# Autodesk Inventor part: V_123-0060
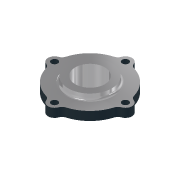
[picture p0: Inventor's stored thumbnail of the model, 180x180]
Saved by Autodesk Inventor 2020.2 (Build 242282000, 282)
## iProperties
Created: 2006-02
Part Number: V_123-0060
Document SubType Name: Modeling
Designer: F.Stasiak
Description: Pokrywka typ1
Material: St 4S
Project: Przekładnia X51
Mass: 230.761 g
Surface Area: 113.991 cm^2
Volume: 29.3963 cm^3
Density: 7.85 g/cm^3
Appearance: Brąz armatni (nowy/polerowany)
Manager: www.cadconsulting.pl
Company: Fabian Stasiak CAD Consulting
Author: F.Stasiak
Subject: Zbiór ćwiczeń. Autodesk Inventor 2020. Kurs podstawowy
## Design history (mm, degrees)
sketch "Szkic1"
  geometry: C1 r 32.5 at (0, -38.423); A1 r 23.5 centre (0, -38.423) between (0, -14.923) and (0, -61.923) reference
  constraints: 1 centre point, 1 coincident
  dimensions: "d0" = 65 diameter of C1
extrude "Wyciągnięcie proste1" new body sketch "Szkic1" distance "d1" = 8; taper "d2" = 0 deg
sketch "Szkic2"
  geometry: C1 r 16.02 at (0, 0) reference
extrude "Wyciągnięcie proste2" join sketch "Szkic2" distance "d3" = 9.6; taper "d4" = 0 deg
sketch "Szkic4"
  geometry: C1 r 12.5 at (0, 0) reference; C2 r 13.5 at (0, 0)
  constraints: 1 centre point, 1 coincident
  dimensions: "d30" = 27 diameter of C2
extrude "Wyciągnięcie proste4" cut sketch "Szkic4" extent not by distance; stored distance "d7" = 6.5; taper "d8" = 0 deg
fillet "Zaokrąglenie1" dims "d9" = 5
sketch "Szkic5"
  geometry: L1 (0, 0)-(0, -32.5); C1 r 6 at (0, -32.5)
  constraints: 2 end point, 1 centre point, 1 coincident, 1 vertical, 1 vertical alignment, 1 other
  dimensions: "d10" = 12 diameter of C1
extrude "Wyciągnięcie proste5" join sketch "Szkic5" stored distance "d11" = 6.5; taper "d12" = 0 deg
hole "Otwór1" diameter "d19" = 6; stored, may be unused: countersink angle "d23" = 90 deg, drill point angle "d25" = 118 deg; dims "d17" = 10, "d18" = 10, "d20" = 6, "d21" = 4, "d22" = 2, "d24" = 8
fillet "Zaokrąglenie3" dims "d26" = 5
sketch "Szkic7"
  geometry: C1 r 13.5 at (0, -38.423) reference; C2 r 13.5 at (0, -38.423) reference; C3 r 20 at (0, -38.423)
  constraints: 1 centre point
  dimensions: "d31" = 40 diameter of C3
extrude "Wyciągnięcie proste7" join sketch "Szkic7" distance "d32" = 5; taper "d33" = 0 deg
fillet "Zaokrąglenie4" dims "d34" = 2
pattern_circular "Szyk kołowy2" dims angle "d36" = 360 deg
node "Bryła1"
node "Korpusy bryłowe"
node "Korpusy powierzchniowe"
node "Odniesienie1"
node "Odniesienie2"
node "Odniesienie4"
node "Pętla rzutowana1"
